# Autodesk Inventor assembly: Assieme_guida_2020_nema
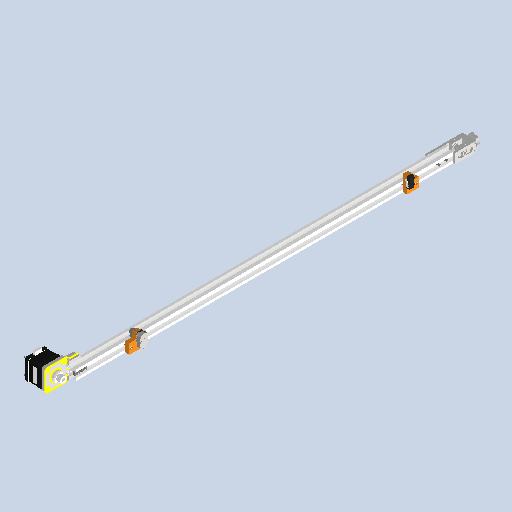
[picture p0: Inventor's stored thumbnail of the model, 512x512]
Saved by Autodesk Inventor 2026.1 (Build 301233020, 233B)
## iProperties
Created: 2026-01
Part Number: Assieme_guida_2020_nema
Document SubType Name: Assembly
Designer: hp
Sending System: Autodesk Inventor 2025
Preprocessor: ST-DEVELOPER v20
Title: Assieme_guida_2020_nema.stp
Author: R5800u
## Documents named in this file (17)
- C:\Users\hp\Documents\Inventor\DOM1_CartesianRobot\Assieme_guida_2020_nema - Copy.iam
- C:\Users\hp\Documents\Inventor\DOM1_CartesianRobot\2020 Belt Tensioner G_K.iam
- C:\Users\hp\Documents\Inventor\DOM1_CartesianRobot\GT2_20T.ipt
- C:\Users\hp\Documents\Inventor\DOM1_CartesianRobot\NO-NC Limit Switch.ipt
- C:\Users\hp\Documents\Inventor\DOM1_CartesianRobot\blocco_sensore.ipt
- C:\Users\hp\Documents\Inventor\DOM1_CartesianRobot\blocco_sensore_MIR.ipt
- C:\Users\hp\Documents\Inventor\DOM1_CartesianRobot\NEMA 42SHDC3030Z.ipt
- C:\Users\hp\Documents\Inventor\DOM1_CartesianRobot\blocco_nema.ipt
- C:\Users\hp\Documents\Inventor\DOM1_CartesianRobot\2020v2.ipt
- C:\Users\hp\Documents\Inventor\Content Center Files\R2026\en-US\ISO 4762(2)\ISO 4762 - M4 x 25ISO.ipt
- C:\Users\hp\Documents\Inventor\Content Center Files\R2026\en-US\ISO 4762(2)\ISO 4762 - M3 x 25ISO.ipt
- C:\Users\hp\Documents\Inventor\Content Center Files\R2021\en-US\ISO 4017(1)\ISO 4017 - M10 x 20 - ISO.ipt
- C:\Users\hp\Documents\Inventor\Content Center Files\R2026\en-US\ISO 4017(1)\ISO 4017 - M4 x 25 - ISO.ipt
- C:\Users\hp\Documents\Inventor\DOM1_CartesianRobot\2020 M4 (1).ipt
- C:\Users\hp\Documents\Inventor\Content Center Files\R2026\en-US\ANSI B18.3.1M(5)\ANSI B18.3.1M - M3x0.5 x 45(3).ipt
- C:\Users\hp\Documents\Inventor\Content Center Files\R2026\en-US\ISO 4032(2)\ISO 4032 - M3 - ISO.ipt
- C:\Users\hp\Documents\Inventor\DOM1_CartesianRobot\2020 M3.ipt
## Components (33 placed, 16 different names)
1. 2020:1
2. 2020 Belt Tensioner G_K:1 [sub-assembly]
3. GT2_20T:1 — Rigid:1
4. NO-NC Limit Switch:1 — Mate:9, Mate:10, Mate:11, Mate:36, Mate:37, Mate:38, Mate:39
5. NO-NC Limit Switch:2 — Mate:17, Mate:18, Mate:19
6. blocco_sensore:1
7. blocco_sensore_MIR:1
8. NEMA 42SHDC3030Z:1
9. blocco_nema:1
10. ISO 4762 M3 x 25:1 — Mate:32, Mate:33, Mate:76
11. ISO 4762 M3 x 25:2 — Mate:34, Mate:35, Mate:77
12. ISO 4017 M10 x 20:1 — Mate:36, Mate:37
13. ISO 4017 M10 x 20:2 — Mate:38, Mate:39
14. ISO 4017 M4 x 25:1 — Mate:40, Mate:41
15. ISO 4017 M4 x 25:2 — Mate:42, Mate:43
16. 2020 M4 (1):1 — Mate:44, Angle:1, Mate:51
17. 2020 M4 (1):2 — Mate:45, Angle:2, Mate:50
18. ISO 4762 M4 x 25:1 — Mate:46, Mate:47, Mate:50
19. ISO 4762 M4 x 25:2 — Mate:48, Mate:49, Mate:51
20. Drilled Forged Hexagon Socket Head Cap Screw - 6 Holes - Metric M3x0.5 x 45:1 — Mate:52, Mate:53
21. ISO 4032 M3:1 — Mate:60, Mate:61
22. Drilled Forged Hexagon Socket Head Cap Screw - 6 Holes - Metric M3x0.5 x 45:2 — Mate:54, Mate:55
23. Drilled Forged Hexagon Socket Head Cap Screw - 6 Holes - Metric M3x0.5 x 45:3 — Mate:56, Mate:57
24. Drilled Forged Hexagon Socket Head Cap Screw - 6 Holes - Metric M3x0.5 x 45:4 — Mate:58, Mate:59
25. ISO 4032 M3:2 — Mate:62, Mate:63
26. ISO 4032 M3:3 — Mate:64, Mate:65
27. ISO 4032 M3:4 — Mate:66, Mate:67
28. ISO 4762 M3 x 25:3 — Mate:68, Mate:69, Mate:79
29. ISO 4762 M3 x 25:4 — Mate:70, Mate:71, Mate:78
30. 2020 M3:1 — Mate:72, Angle:3, Mate:79
31. 2020 M3:2 — Mate:73, Angle:4, Mate:78
32. 2020 M3:5 — Mate:75, Angle:5, Mate:77
33. 2020 M3:6 — Mate:74, Angle:6, Mate:76
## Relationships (61: Mate 54, Angle 6, WeldJoint 1)
- Rigid:1 [WeldJoint]: GT2_20T:1
- Mate:9: NO-NC Limit Switch:1
- Mate:10: NO-NC Limit Switch:1
- Mate:11: NO-NC Limit Switch:1
- Mate:17: NO-NC Limit Switch:2
- Mate:18: NO-NC Limit Switch:2
- Mate:19: NO-NC Limit Switch:2
- Mate:32: ISO 4762 M3 x 25:1
- Mate:33: ISO 4762 M3 x 25:1
- Mate:34: ISO 4762 M3 x 25:2
- Mate:35: ISO 4762 M3 x 25:2
- Mate:36: NO-NC Limit Switch:1 ↔ ISO 4017 M10 x 20:1
- Mate:37: NO-NC Limit Switch:1 ↔ ISO 4017 M10 x 20:1
- Mate:38: NO-NC Limit Switch:1 ↔ ISO 4017 M10 x 20:2
- Mate:39: NO-NC Limit Switch:1 ↔ ISO 4017 M10 x 20:2
- Mate:40: ISO 4017 M4 x 25:1
- Mate:41: ISO 4017 M4 x 25:1
- Mate:42: ISO 4017 M4 x 25:2
- Mate:43: ISO 4017 M4 x 25:2
- Mate:44: 2020 M4 (1):1
- Mate:45: 2020 M4 (1):2
- Angle:1: 2020 M4 (1):1
- Angle:2: 2020 M4 (1):2
- Mate:46: ISO 4762 M4 x 25:1
- Mate:47: ISO 4762 M4 x 25:1
- Mate:48: ISO 4762 M4 x 25:2
- Mate:49: ISO 4762 M4 x 25:2
- Mate:50: 2020 M4 (1):2 ↔ ISO 4762 M4 x 25:1
- Mate:51: 2020 M4 (1):1 ↔ ISO 4762 M4 x 25:2
- Mate:52: Drilled Forged Hexagon Socket Head Cap Screw - 6 Holes - Metric M3x0.5 x 45:1
- Mate:53: Drilled Forged Hexagon Socket Head Cap Screw - 6 Holes - Metric M3x0.5 x 45:1
- Mate:54: Drilled Forged Hexagon Socket Head Cap Screw - 6 Holes - Metric M3x0.5 x 45:2
- Mate:55: Drilled Forged Hexagon Socket Head Cap Screw - 6 Holes - Metric M3x0.5 x 45:2
- Mate:56: Drilled Forged Hexagon Socket Head Cap Screw - 6 Holes - Metric M3x0.5 x 45:3
- Mate:57: Drilled Forged Hexagon Socket Head Cap Screw - 6 Holes - Metric M3x0.5 x 45:3
- Mate:58: Drilled Forged Hexagon Socket Head Cap Screw - 6 Holes - Metric M3x0.5 x 45:4
- Mate:59: Drilled Forged Hexagon Socket Head Cap Screw - 6 Holes - Metric M3x0.5 x 45:4
- Mate:60: ISO 4032 M3:1
- Mate:61: ISO 4032 M3:1
- Mate:62: ISO 4032 M3:2
- Mate:63: ISO 4032 M3:2
- Mate:64: ISO 4032 M3:3
- Mate:65: ISO 4032 M3:3
- Mate:66: ISO 4032 M3:4
- Mate:67: ISO 4032 M3:4
- Mate:68: ISO 4762 M3 x 25:3
- Mate:69: ISO 4762 M3 x 25:3
- Mate:70: ISO 4762 M3 x 25:4
- Mate:71: ISO 4762 M3 x 25:4
- Mate:72: 2020 M3:1
- Mate:73: 2020 M3:2
- Angle:3: 2020 M3:1
- Angle:4: 2020 M3:2
- Mate:74: 2020 M3:6
- Mate:75: 2020 M3:5
- Angle:5: 2020 M3:5
- Angle:6: 2020 M3:6
- Mate:76: ISO 4762 M3 x 25:1 ↔ 2020 M3:6
- Mate:77: ISO 4762 M3 x 25:2 ↔ 2020 M3:5
- Mate:78: ISO 4762 M3 x 25:4 ↔ 2020 M3:2
- Mate:79: ISO 4762 M3 x 25:3 ↔ 2020 M3:1
